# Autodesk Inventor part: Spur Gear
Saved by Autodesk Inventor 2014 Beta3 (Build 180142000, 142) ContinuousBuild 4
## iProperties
Created: 2011-01
Part Number: Spur Gear
Material: Steel
Document SubType Name: Modeling
Designer: Beta-8540w
Categories: <?xml version="1.0" encoding="UTF-16"?> <MemberInstance><Categories><FamilyTemplate><FamilyTemplateParameter ValueType="xs:double" Id="1" ObjectReferenceKey="da
Density: 1 g/cm^3
Appearance: Steel
CustomPartVersion: 1
Author: Beta-8540w
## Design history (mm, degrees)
sketch "Sketch1"
  geometry: C1 r 40.8 at (0, 0)
  constraints: 1 centre point
  dimensions: "d0" = 81.6 diameter of C1 (= da_da)
extrude "Extrusion1" new body sketch "Sketch1" distance "d1" = 13 (= da_b); taper "d2" = 0 deg
workplane "Work Plane2"
sketch "Sketch2"
  geometry: C1 r 40.8 at (0, 0) reference; C2 r 40 at (0, 0)
  constraints: 1 centre point, 1 coincident
  dimensions: "d3" = 80 diameter of C2 (= da_dw)
feature "Pitch Diameter" sketch "Sketch2" dims "d4" = 10, "d5" = 0
workplane "Work Plane8"
workplane "Work Plane9"
feature "Spur Gear" dims "da_b" = 13, "da_d" = 80, "da_aw" = 50, "da_da" = 81.6, "da_df" = 78, "da_dw" = 80, angle "da_beta" = 0 deg, "da_lefttooth" = 0, "da_righttooth" = 0
node "Keyway1"
body "Solid1"
body "Srf1"
feature "Hub Keyway"
other parameters: "d17" = 0, "d34" = 0.31416 (computed from da_z), "d39" = 0, "d41" = 0, "d47" = 0, "d48" = 0
